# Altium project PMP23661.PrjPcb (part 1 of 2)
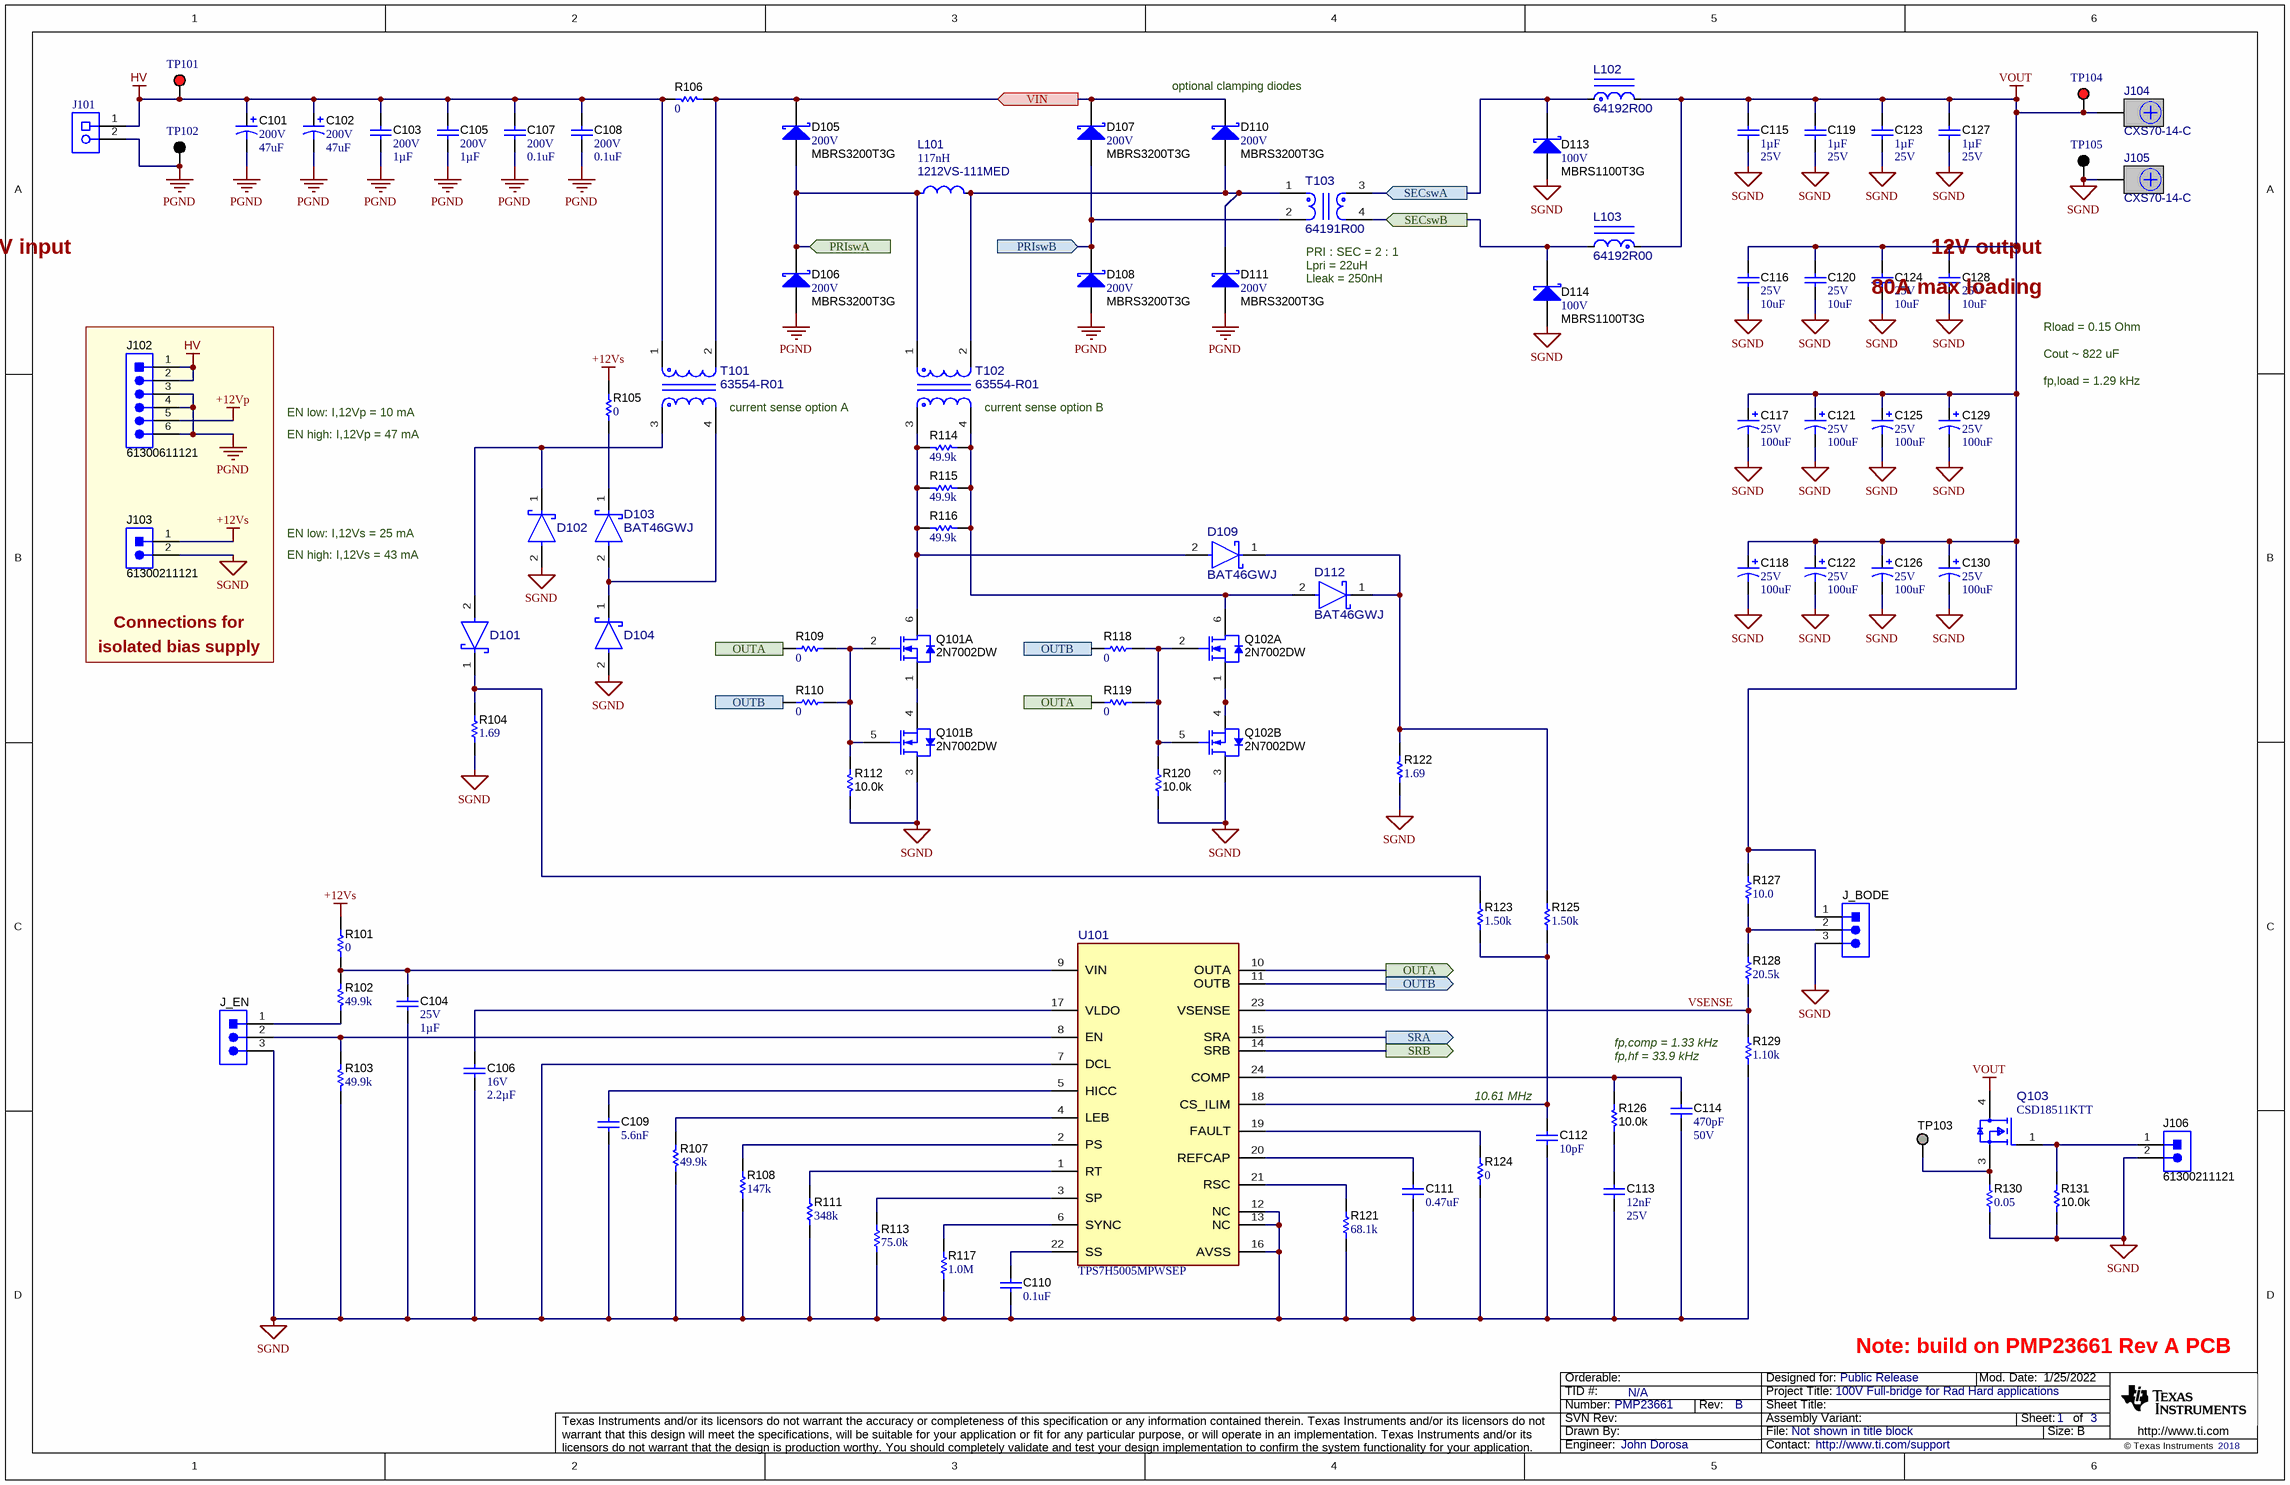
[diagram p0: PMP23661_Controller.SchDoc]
TID: N/A; TechSupport: http://www.ti.com/support; SCH_Rev: B; PRJ_Title: 100V Full-bridge for Rad Hard applications; PRJ_Number: PMP23661; PRJ_Engineer: John Dorosa; PRJ_Customer: Public Release; PCB_Rev: A; PCB_Layout: John Dorosa; CopyrightYear: 2018
3 sheets, 236 parts. Net scope: flat (ports and power ports of the same name join across sheets).
Board file: PMP23661.PcbDoc
Sheets:
  PMP23661_Controller.SchDoc
  PMP23661_Primary Drivers.SchDoc
  PMP23661_Secondary Drivers.SchDoc

## Sheet PMP23661_Controller.SchDoc
size 431 x 279 mm; Date: Not shown in title block; ApprovedBy: Not shown in title block; CheckedBy: Not shown in title block; Author: Not shown in title block; CompanyName: Not shown in title block; Engineer: Not shown in title block; Organization: Not shown in title block; Address1: Not shown in title block; Address2: Not shown in title block; Address3: Not shown in title block; Address4: Not shown in title block; DocumentNumber: 1; Revision: Use project parameter SCH_Rev; SheetNumber: 1; SheetTotal: 3; PageSetup: Record=PageOptions¦CenterHorizontal=True¦CenterVertical=True¦PrintScale=1.00¦XCorrection=1.00¦YCorrection=1.00¦PrintKind=0¦BorderSize=5000000¦LeftOffset=0¦BottomOffset=0¦Orientation=2¦PaperLength=1000¦PaperWidth=1000¦Scale=100¦PaperSource=15¦PrintQuality=600¦MediaType=1¦DitherType=10¦PaperKind=Letter¦PrintScaleMode=1

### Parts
C101  VDC_V: 200V  ValueDisplayed: 47uF  [EB_K16]  (hidden comment: EEV-EB2D470SM)
C102  VDC_V: 200V  ValueDisplayed: 47uF  [EB_K16]  (hidden comment: EEV-EB2D470SM)
C103  VDC_V: 200V  ValueDisplayed: 1µF  [1812_280]  (hidden comment: 18122C105KAT2A)
C104  VDC_V: 25V  Cap_F: 1µF  [0603_HV]  (hidden comment: GRM188R71E105KA12D)
C105  VDC_V: 200V  ValueDisplayed: 1µF  [1812_280]  (hidden comment: 18122C105KAT2A)
C106  VDC_V: 16V  Cap_F: 2.2µF  [0603_HV]  (hidden comment: GRM188Z71C225KE43)
C107  VDC_V: 200V  ValueDisplayed: 0.1uF  [1206_180]  (hidden comment: GRM31CR72D104KW03L)
C108  VDC_V: 200V  ValueDisplayed: 0.1uF  [1206_180]  (hidden comment: GRM31CR72D104KW03L)
C109  Cap_F: 5.6nF  [0603_HV]  (hidden comment: GRM188R71E562KA01D)
C110  value 0.1uF  [0603_HV]  (hidden comment: GCM188R71E104KA57D)
C111  value 0.47uF  [0603_HV]  (hidden comment: GCM188R71C474KA55D)
C112  ValueDisplayed: 10pF  [0603_HV]  (hidden comment: GCM1885C2A100JA16D)
C113  Cap_F: 12nF  VDC_V: 25V  [0603_HV]  (hidden comment: GRM188R71E123KA01D)
C114  Cap_F: 470pF  VDC_V: 50V  [0603_HV]  (hidden comment: GRM188R71H471KA01D)
C115  Cap_F: 1µF  VDC_V: 25V  [0805_HV]  (hidden comment: C0805C105K3RACTU)
C116  VDC_V: 25V  ValueDisplayed: 10uF  [1210_280]  (hidden comment: C1210C106K3RACTU)
C117  VDC_V: 25V  ValueDisplayed: 100uF  [7360-38]  (hidden comment: T495E107K025ATE100)
C118  VDC_V: 25V  ValueDisplayed: 100uF  [7360-38]  (hidden comment: T495E107K025ATE100)
C119  Cap_F: 1µF  VDC_V: 25V  [0805_HV]  (hidden comment: C0805C105K3RACTU)
C120  VDC_V: 25V  ValueDisplayed: 10uF  [1210_280]  (hidden comment: C1210C106K3RACTU)
C121  VDC_V: 25V  ValueDisplayed: 100uF  [7360-38]  (hidden comment: T495E107K025ATE100)
C122  VDC_V: 25V  ValueDisplayed: 100uF  [7360-38]  (hidden comment: T495E107K025ATE100)
C123  Cap_F: 1µF  VDC_V: 25V  [0805_HV]  (hidden comment: C0805C105K3RACTU)
C124  VDC_V: 25V  ValueDisplayed: 10uF  [1210_280]  (hidden comment: C1210C106K3RACTU)
C125  VDC_V: 25V  ValueDisplayed: 100uF  [7360-38]  (hidden comment: T495E107K025ATE100)
C126  VDC_V: 25V  ValueDisplayed: 100uF  [7360-38]  (hidden comment: T495E107K025ATE100)
C127  Cap_F: 1µF  VDC_V: 25V  [0805_HV]  (hidden comment: C0805C105K3RACTU)
C128  VDC_V: 25V  ValueDisplayed: 10uF  [1210_280]  (hidden comment: C1210C106K3RACTU)
C129  VDC_V: 25V  ValueDisplayed: 100uF  [7360-38]  (hidden comment: T495E107K025ATE100)
C130  VDC_V: 25V  ValueDisplayed: 100uF  [7360-38]  (hidden comment: T495E107K025ATE100)
D101  BAT46GWJ  [FP-BAT46GWJ_SOD-123-MFG]  (value not drawn)
D102  BAT46GWJ  [FP-BAT46GWJ_SOD-123-MFG]  (value not drawn)
D103  BAT46GWJ  [FP-BAT46GWJ_SOD-123-MFG]
D104  BAT46GWJ  [FP-BAT46GWJ_SOD-123-MFG]  (value not drawn)
D105  MBRS3200T3G  value 200V  [SMB]
D106  MBRS3200T3G  value 200V  [SMB]
D107  MBRS3200T3G  value 200V  [SMB]
D108  MBRS3200T3G  value 200V  [SMB]
D109  BAT46GWJ  [FP-BAT46GWJ_SOD-123-MFG]
D110  MBRS3200T3G  value 200V  [SMB]
D111  MBRS3200T3G  value 200V  [SMB]
D112  BAT46GWJ  [FP-BAT46GWJ_SOD-123-MFG]
D113  MBRS1100T3G  value 100V  [SMB]
D114  MBRS1100T3G  value 100V  [SMB]
J101  ED120/2DS  [On-Shore_ED120_2DS]  (value not drawn)
J102  61300611121  [WURTH_61300611121]
J103  61300211121  [WURTH_61300211121]
J104  CXS70-14-C  [Panduit_CXS70-14-C]
J105  CXS70-14-C  [Panduit_CXS70-14-C]
J106  61300211121  [WURTH_61300211121]
J_BODE  61300311121  [WURTH_61300311121]  (value not drawn)
J_EN  61300311121  [WURTH_61300311121]  (value not drawn)
L101  1212VS-111MED  value 117nH  [FP-1212VS-111MED_SMT_IND_11MM5_12MM0-MFG]
L102  64192R00  [FP-64192R00_PTH_IND_48MM0_33MM0-MFG]
L103  64192R00  [FP-64192R00_PTH_IND_48MM0_33MM0-MFG]
Q101  2N7002DW  [SOT-363]  (parts A,B of 2)
Q102  2N7002DW  [SOT-363]  (parts A,B of 2)
Q103  CSD18511KTT  [KTT0002A-MFG]
R101  ValueDisplayed: 0  [0603_HV]  (hidden comment: CRCW06030000Z0EA)
R102  ValueDisplayed: 49.9k  [0603_HV]  (hidden comment: CRCW060349K9FKEA)
R103  ValueDisplayed: 49.9k  [0603_HV]  (hidden comment: CRCW060349K9FKEA)
R104  ValueDisplayed: 1.69  [1206]  (hidden comment: CRCW12061R69FKEA)
R105  ValueDisplayed: 0  [0603_HV]  (hidden comment: CRCW06030000Z0EA)
R106  ValueDisplayed: 0  [2512_WIDE_VISHAY]  (hidden comment: RCL12250000Z0EG)
R107  ValueDisplayed: 49.9k  [0603_HV]  (hidden comment: CRCW060349K9FKEA)
R108  ValueDisplayed: 147k  [0603_HV]  (hidden comment: CRCW0603147KFKEA)
R109  ValueDisplayed: 0  [0603_HV]  (hidden comment: CRCW06030000Z0EA)
R110  ValueDisplayed: 0  [0603_HV]  (hidden comment: CRCW06030000Z0EA)
R111  ValueDisplayed: 348k  [0603_HV]  (hidden comment: CRCW0603348KFKEA)
R112  ValueDisplayed: 10.0k  [0603_HV]  (hidden comment: CRCW060310K0FKEA)
R113  ValueDisplayed: 75.0k  [0603_HV]  (hidden comment: CRCW060375K0FKEA)
R114  ValueDisplayed: 49.9k  [0603_HV]  (hidden comment: CRCW060349K9FKEA)
R115  ValueDisplayed: 49.9k  [0603_HV]  (hidden comment: CRCW060349K9FKEA)
R116  ValueDisplayed: 49.9k  [0603_HV]  (hidden comment: CRCW060349K9FKEA)
R117  ValueDisplayed: 1.0M  [0603_HV]  (hidden comment: CRCW06031M00JNEA)
R118  ValueDisplayed: 0  [0603_HV]  (hidden comment: CRCW06030000Z0EA)
R119  ValueDisplayed: 0  [0603_HV]  (hidden comment: CRCW06030000Z0EA)
R120  ValueDisplayed: 10.0k  [0603_HV]  (hidden comment: CRCW060310K0FKEA)
R121  ValueDisplayed: 68.1k  [0603_HV]  (hidden comment: CRCW060368K1FKEA)
R122  ValueDisplayed: 1.69  [1206]  (hidden comment: CRCW12061R69FKEA)
R123  ValueDisplayed: 1.50k  [0603_HV]  (hidden comment: CRCW06031K50FKEA)
R124  ValueDisplayed: 0  [0603_HV]  (hidden comment: CRCW06030000Z0EA)
R125  ValueDisplayed: 1.50k  [0603_HV]  (hidden comment: CRCW06031K50FKEA)
R126  ValueDisplayed: 10.0k  [0603_HV]  (hidden comment: CRCW060310K0FKEA)
R127  ValueDisplayed: 10.0  [0603_HV]  (hidden comment: CRCW060310R0FKEA)
R128  ValueDisplayed: 20.5k  [0603_HV]  (hidden comment: CRCW060320K5FKEA)
R129  ValueDisplayed: 1.10k  [0603_HV]  (hidden comment: CRCW06031K10FKEA)
R130  ValueDisplayed: 0.05  [3518_WIDE]  (hidden comment: FCSL90R050FER)
R131  ValueDisplayed: 10.0k  [0603_HV]  (hidden comment: CRCW060310K0FKEA)
T101  63554-R01  [FP-63554-R01_SMT_XFRMR_24MM0_20MM0-MFG]
T102  63554-R01  [FP-63554-R01_SMT_XFRMR_24MM0_20MM0-MFG]
T103  64191R00  [FP-64191R00_PTH_XFRMR_55MM0_48MM0-MFG]
TP101  5010  [Keystone5010]  (value not drawn)
TP102  5011  [Keystone5011]  (value not drawn)
TP103  TP_SM_1MM  [TP_SM_1MM]  (value not drawn)  (no BOM)
TP104  5010  [Keystone5010]  (value not drawn)
TP105  5011  [Keystone5011]  (value not drawn)
U101  TPS7H5005MPWSEP  [PW0024A-MFG]

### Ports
OUTA (in), OUTA (out), OUTB (in), OUTB (out), PRIswA (in), PRIswB (in), SECswA (in), SECswB (in), SRA (out), SRB (out), VIN (in)

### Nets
+12Vp: J102.5
+12Vs: J103.1 R101.2 R105.1
HV: C101.1(+) C102.1(+) C103.1 C105.1 C107.1 C108.1 J101.1 J102.1 J102.2 R106.2 T101.1 TP101.1
PGND: C101.2(-) C102.2(-) C103.2 C105.2 C107.2 C108.2 D106.2(A) D108.2(A) D111.2(A) J101.2 J102.3 J102.4 J102.6 TP102.1
SGND: C104.2 C106.1 C109.1 C110.2 C111.1 C112.2 C113.2 C114.2 C115.2 C116.2 C117.2(-) C118.2(-) C119.2 C120.2 C121.2(-) C122.2(-) C123.2 C124.2 C125.2(-) C126.2(-) C127.2 C128.2 C129.2(-) C130.2(-) D102.2(ANODE) D104.2(ANODE) D113.2(A) D114.2(A) J103.2 J105.1 J106.2 J_BODE.3 J_EN.3 Q101.3(D) Q102.3(D) R103.2 R104.1 R107.2 R108.1 R111.1 R112.1 R113.1 R117.1 R120.1 R121.1 R122.1 R124.2 R129.1 R130.1 R131.1 TP105.1 U101.7(DCL) U101.12(NC) U101.13(NC) U101.16(AVSS)
VOUT: C115.1 C116.1 C117.1(+) C118.1(+) C119.1 C120.1 C121.1(+) C122.1(+) C123.1 C124.1 C125.1(+) C126.1(+) C127.1 C128.1 C129.1(+) C130.1(+) J104.1 J_BODE.1 L102.2 L103.1 Q103.4(Drain) R127.2 TP104.1
OUTA: R109.2 R119.2 U101.10(OUTA) ; port OUTA
OUTB: R110.2 R118.2 U101.11(OUTB) ; port OUTB
PRIswA: D105.2(A) D106.1(K) L101.1 T102.1 ; port PRIswA
PRIswB: D107.2(A) D108.1(K) T103.2 ; port PRIswB
SECswA: D113.1(K) L102.1 T103.3 ; port SECswA
SECswB: D114.1(K) L103.2 T103.4 ; port SECswB
SRA: U101.15(SRA) ; port SRA
SRB: U101.14(SRB) ; port SRB
VIN: D105.1(K) D107.1(K) D110.1(K) R106.1 T101.2 ; port VIN
VSENSE: R128.1 R129.2 U101.23(VSENSE)
NetC104_1: C104.1 R101.1 R102.1 U101.9(VIN)
NetC106_2: C106.2 U101.17(VLDO)
NetC109_2: C109.2 U101.5(HICC)
NetC110_1: C110.1 U101.22(SS)
NetC111_2: C111.2 U101.20(REFCAP)
NetC112_1: C112.1 R123.1 R125.1 U101.18(CS_ILIM)
NetC113_1: C113.1 R126.1
NetC114_1: C114.1 R126.2 U101.24(COMP)
NetD101_1: D101.1(CATHODE) R104.2 R123.2
NetD101_2: D101.2(ANODE) D102.1(CATHODE) T101.3
NetD103_1: D103.1(CATHODE) R105.2
NetD103_2: D103.2(ANODE) D104.1(CATHODE) T101.4
NetD109_1: D109.1(CATHODE) D112.1(CATHODE) R122.2 R125.2
NetD109_2: D109.2(ANODE) Q101.6(D) R114.1 R115.1 R116.1 T102.3
NetD110_2: D110.2(A) D111.1(K) L101.2 T102.2 T103.1
NetD112_2: D112.2(ANODE) Q102.6(D) R114.2 R115.2 R116.2 T102.4
NetJ106_1: J106.1 Q103.1(Gate) R131.2
NetJ_BODE_2: J_BODE.2 R127.1 R128.2
NetJ_EN_1: J_EN.1 R102.2
NetJ_EN_2: J_EN.2 R103.1 U101.8(EN)
NetQ101_1: Q101.1(S) Q101.4(S)
NetQ101_2: Q101.2(G) Q101.5(G) R109.1 R110.1 R112.2
NetQ102_1: Q102.1(S) Q102.4(S)
NetQ102_2: Q102.2(G) Q102.5(G) R118.1 R119.1 R120.2
NetQ103_3: Q103.3(Source) R130.2 TP103.1
NetR107_1: R107.1 U101.4(LEB)
NetR108_2: R108.2 U101.2(PS)
NetR111_2: R111.2 U101.1(RT)
NetR113_2: R113.2 U101.3(SP)
NetR117_2: R117.2 U101.6(SYNC)
NetR121_2: R121.2 U101.21(RSC)
NetR124_1: R124.1 U101.19(FAULT)

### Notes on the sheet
- (near D110) optional clamping diodes
- 70 - 110V input
- (near T103) PRI : SEC = 2 : 1
- (near T103) Lpri = 22uH
- Lleak = 250nH
- 12V output
- 80A max loading
- Rload = 0.15 Ohm
- Cout ~ 822 uF
- EN low: I,12Vp = 10 mA
- EN high: I,12Vp = 47 mA
- (near T101) current sense option A
- (near T102) current sense option B
- fp,load = 1.29 kHz
- EN low: I,12Vs = 25 mA
- EN high: I,12Vs = 43 mA
- Connections for
- isolated bias supply
- (near C112) 10.61 MHz
- fp,hf = 33.9 kHz
- (near R129) fp,comp = 1.33 kHz
- Note: build on PMP23661 Rev A PCB

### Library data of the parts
C101 C102 = CMP-0011430-2: CAP, AL, 47 uF, 200 V, +/- 20%, SMD; Manufacturer: Panasonic; TaMin_C: -25°C; Polarized: Y; SizeAreaWB_mm2: 483; Value1: Unknown; U/M: EA; Value: 47uF; TaMax_C: 105°C; SizeZ_mm: 16.5; SizeX_mm: 21; SizeY_mm: 19; Cap_Case: 18x16.5; SizeArea_mm2: 399; CompType: Capacitor; AEC Qualified: N; Cap_F: 47µF; IRMS_A: 600mA; AEC Category: Q200
C103 C105 = CMP-0081058-1: CAP, CERM, 1 µF, 200 V,+/- 10%, X7R, 1812; Manufacturer: AVX; TaMin_C: -55°C; Polarized: N; SizeAreaWB_mm2: 23.1; U/M: EA; Value: 1uF; TaMax_C: 125°C; SizeZ_mm: 2.8; SizeX_mm: 4.5; SizeY_mm: 3.2; SizeArea_mm2: 14.4; AEC Category: Q200
C104 = CMP-0007405-5: CAP, CERM, 1 uF, 25 V, +/- 10%, X7R, 0603; Manufacturer: MuRata; Cap_Case: 0603; AEC Category: Q200; Value: 1uF; SizeX_mm: 1.6; U/M: EA; Value1: Unknown; SizeAreaWB_mm2: 4.68; SizeY_mm: 0.8; TaMin_C: -55°C; SizeZ_mm: 1; Polarized: N; MFG_Status: TI_Obsolete; TaMax_C: 125°C; SizeArea_mm2: 1.28
C106 = CMP-0007499-4: CAP, CERM, 2.2 uF, 16 V, +/- 10%, X7R, 0603; Manufacturer: MuRata; TaMin_C: -55°C; Polarized: N; SizeAreaWB_mm2: 4.68; Value1: Unknown; U/M: EA; Value: 2.2uF; TaMax_C: 125°C; SizeZ_mm: 1; SizeX_mm: 1.6; SizeY_mm: 0.8; Cap_Case: 0603; SizeArea_mm2: 1.28; AEC Category: Q200
C107 C108 = CMP-0008972-2: CAP, CERM, 0.1 uF, 200 V, +/- 10%, X7R, 1206; Manufacturer: MuRata; TaMin_C: -55°C; Polarized: N; SizeAreaWB_mm2: 10.92; Value1: Unknown; U/M: EA; Value: 0.1uF; TaMax_C: 125°C; SizeZ_mm: 1.8; SizeX_mm: 3.2; SizeY_mm: 1.6; Cap_Case: 3.2x16x16mm; SizeArea_mm2: 5.12; Cap_F: 100nF; AEC Category: Q200
C109 = CMP-0007425-5: CAP, CERM, 5600 pF, 25 V, +/- 10%, X7R, 0603; Manufacturer: MuRata; ValueDisplayed: 5600pF; SizeArea_mm2: 1.28; SizeZ_mm: 1; Value2: 25V; MFG_Status: TI_Obsolete; SizeX_mm: 1.6; Value1: Unknown; AEC Category: Q200; Value: 5600pF; SizeAreaWB_mm2: 4.68; Polarized: N; Cap_Case: 0603; U/M: EA; TaMin_C: -55°C; TaMax_C: 125°C; SizeY_mm: 0.8
C110 = CMP-0084679-1: CAP, CERM, 0.1 µF, 25 V,+/- 10%, X7R, AEC-Q200 Grade 1, 0603; Manufacturer: MuRata; VDC_V: 25V; TaMin_C: -55°C; SizeY_mm: 0.8; Polarized: N; SizeArea_mm2: 1.28; Cap_Case: 0603; SizeZ_mm: 1; SizeX_mm: 1.6; AEC Qualified: Y; AEC Category: Q200; ValueDisplayed: 0.1µF; TaMax_C: 125°C; U/M: EA; SizeAreaWB_mm2: 4.68; Cap_F: 100nF
C111 = CMP-0007138-4: CAP, CERM, 0.47 uF, 16 V, +/- 10%, X7R, AEC-Q200 Grade 1, 0603; Manufacturer: MuRata; TaMin_C: -55°C; Polarized: N; SizeAreaWB_mm2: 4.68; Value1: Unknown; U/M: EA; TaMax_C: 125°C; SizeZ_mm: 1; SizeX_mm: 1.6; SizeY_mm: 0.8; Cap_Case: 0603; Value2: 16V; SizeArea_mm2: 1.28; AEC Qualified: Y; Cap_F: 470nF; AEC Category: Q200
C112 = CMP-0084283-1: CAP, CERM, 10 pF, 100 V,+/- 5%, C0G/NP0, AEC-Q200 Grade 1, 0603; Manufacturer: MuRata; TaMax_C: 125°C; Cap_Case: 0603; Value2: 100V; SizeX_mm: 1.6; SizeY_mm: 0.8; SizeArea_mm2: 1.28; Polarized: N; AEC Category: Q200; SizeAreaWB_mm2: 4.68; AEC Qualified: Y; SizeZ_mm: 1; Value: 10pF; U/M: EA; TaMin_C: -55°C
C113 = CMP-0007407-5: CAP, CERM, 0.012 uF, 25 V, +/- 10%, X7R, 0603; Manufacturer: MuRata; SizeZ_mm: 1; SizeX_mm: 1.6; Polarized: N; SizeY_mm: 0.8; AEC Category: Q200; MFG_Status: TI_Obsolete; SizeAreaWB_mm2: 4.68; Cap_Case: 0603; SizeArea_mm2: 1.28; TaMax_C: 125°C; Value1: Unknown; U/M: EA; TaMin_C: -55°C
C114 = CMP-0007455-4: CAP, CERM, 470 pF, 50 V, +/- 10%, X7R, 0603; Manufacturer: MuRata; TaMin_C: -55°C; Polarized: N; SizeAreaWB_mm2: 4.68; Value1: Unknown; U/M: EA; Value: 470pF; TaMax_C: 125°C; SizeZ_mm: 1; SizeX_mm: 1.6; SizeY_mm: 0.8; Cap_Case: 0603; SizeArea_mm2: 1.28; AEC Category: Q200
C115 C119 C123 C127 = CMP-0007728-2: CAP, CERM, 1 uF, 25 V, +/- 10%, X7R, 0805; Manufacturer: Kemet; TaMin_C: -55°C; Polarized: N; SizeAreaWB_mm2: 6.75; Value1: Unknown; U/M: EA; Value: 1uF; TaMax_C: 125°C; SizeZ_mm: 1.45; SizeX_mm: 2; SizeY_mm: 1.25; Cap_Case: 0805; SizeArea_mm2: 2.5; AEC Category: Q200
C116 C120 C124 C128 = CMP-0009078-1: CAP, CERM, 10 uF, 25 V, +/- 10%, X7R, 1210; Manufacturer: Kemet; TaMin_C: -55°C; Polarized: N; SizeAreaWB_mm2: 14.7; Value1: Unknown; U/M: EA; Value: 10uF; TaMax_C: 125°C; SizeZ_mm: 2.8; SizeX_mm: 3.2; SizeY_mm: 2.5; Cap_Case: 1210; SizeArea_mm2: 8; Cap_F: 10µF; AEC Category: Q200
C117 C118 C121 C122 C125 C126 C129 C130 = CMP-0012025-2: CAP, TA, 100 uF, 25 V, +/- 10%, 0.1 ohm, SMD; Manufacturer: Kemet; TaMin_C: -55°C; ESR_ohm: 0.1; Polarized: Y; SizeAreaWB_mm2: 74.4; Value1: 0.1 ohm; U/M: EA; Value: 100uF; TaMax_C: 125°C; SizeZ_mm: 3.8; SizeX_mm: 7.3; SizeY_mm: 6; Cap_Case: E; SizeArea_mm2: 43.8; CompType: Capacitor; AEC Qualified: N; Cap_F: 100µF; IRMS_A: 1.273A; AEC Category: Q200
D101-D104 D109 D112 = CMP-0090343-1: Diode Schottky 100V 250mA (DC) Surface Mount SOD-123; Manufacturer: Nexperia; SizeZ_mm: 1.3mm; Peak Reverse Current: 2uA; TaMin_C: -55°C; Cap_F: 39pF; TJmax_C: 150°C; AEC Grade: Grade 0; Max Surge Forward Current: 2.5A; Standoff Height: 0mm; TaMax_C: +150°C; AEC Qualified: Yes
D105-D108 D110 D111 = CMP-0028599-2: Diode, Schottky, 200 V, 3 A, SMB; Manufacturer: ON Semiconductor; Io_A: 3A; SizeY_mm: 3.81; RJC_CperW: 62; SizeX_mm: 5.6; TJmax_C: 175°C; Vf_V: 840mV; SizeZ_mm: 2.6; Green_REACh: Incomplete; Green_Lifecycle: Not Set; AEC Category: Q101; SizeAreaWB_mm2: 44.156; Value2: 0.84V; SizeArea_mm2: 21.336
D113 D114 = CMP-0028521-2: Diode, Schottky, 100 V, 1 A, SMB; Manufacturer: ON Semiconductor; TJmax_C: 150°C; SizeY_mm: 3.81; RJC_CperW: 22; Value1: 1A; SizeAreaWB_mm2: 44.156; Green_Lifecycle: Active; SizeArea_mm2: 21.336; Vf_V: 750mV; SizeZ_mm: 2.6; SizeX_mm: 5.6; Green_REACh: Passed; Value2: 0.75V; AEC Category: Q101
J101 = CMP-0074910-1: Terminal Block, 5.08 mm, 2x1, Brass, TH; Manufacturer: On-Shore Technology; Cert_VDE: Y; CNHeader: False; Current_A: 15A; Green_Lifecycle: Not Set; Shrouded: N; Gender: Female; Green_REACh: Incomplete; Voltage_V: 300V; Row_Count: 1; Pitch_mm: 5.08; CT: True
J102 = CMP-0054801-2: Header, 2.54 mm, 6x1, Gold, TH; Manufacturer: Wurth Elektronik; Cert_UL: Y; Gender: Male; Row_Count: 1; Shrouded: N; Pitch_mm: 2.54
J103 J106 = CMP-0054794-2: Header, 2.54 mm, 2x1, Gold, TH; Manufacturer: Wurth Elektronik; Shrouded: N; Gender: Male; Green_REACh: Passed; Pitch_mm: 2.54; Green_Lifecycle: Active; Row_Count: 1; Cert_UL: Y
J104 J105 = CMP-0075010-2: Terminal 70A Lug; Manufacturer: Panduit; CompType: Screw Terminal; CT: False; Green_Lifecycle: Not Set; Green_REACh: Incomplete
J_BODE J_EN = CMP-0054796-4: Header, 2.54 mm, 3x1, Gold, TH; Manufacturer: Wurth Elektronik; Green_REACh: Passed; CT: FALSE; CNHeader: TRUE; Green_Lifecycle: Active
L101 = CMP-0125020-1: Air Core Inductor, High Current, 117 nH, 44 A, 1212VS Series, ± 20%, 0.00143 ohm, 399 MHz; Manufacturer: Coilcraft; AEC Qualified: No; DCR_ohm: 1.43m; Irms: 44A; SizeZ_mm: 11.3mm; Q Factor: 165; Self Resonant Frequency: 399MHz; TaMax_C: +125°C; TaMin_C: -40°C; Test Frequency: 1MHz
L102 L103 = CMP-0127672-1: 2uH & 48.7Ap INDUCTOR; Manufacturer: Payton Planar; Ind_H: 2µH; Irms: 48.7A; SizeZ_mm: 13mm
Q101 Q102 = CMP-0000770-1: MOSFET, 2-CH, N-CH, 60 V, 0.115 A, SOT-363; Alternate Manufacturer: None; Manufacturer: Fairchild Semiconductor; SizeZ_mm: 1.1; ChType: N; VdsMax_V: 60V; SizeX_mm: 2.2; Vgs_V: 20V; Value: 60V; SizeArea_mm2: 4.84; AEC Category: Q101; IdsMax_A: 115mA; SizeAreaWB_mm2: 10.24; U/M: EA
Q103 = CMP-0097579-1: MOSFET N-Channel 40 V 194A (Ta) 188W (Ta) Surface Mount DDPAK/TO-263-3; Manufacturer: Texas Instruments; Turn On Delay Time: 8ns; TJmax_C: +175°C; SizeZ_mm: 4.95mm; Standoff Height: 0mm; Reverse Recovery Charge: 62nC; Transconductance: 249S; IdsMax_A: 110A; Number Of N Channels: 1; AEC Qualified: No; Max Forward Diode Voltage: 1V; Rdson45_ohm: 2.1mΩ; VdsMax_V: 40V; QgTyp_nC: 64nC @ 10V; Input Capacitace At Vds: 4570pF @ 20V; Vgs_V: 20V; Turn Off Delay Time: 17ns; Threshold Vgs Min: 1.5V; Pulse Drain Current: 400A; Reverse Recovery Time: 31ns; Threshold Vgs Max: 2.4V; ChMode: False; Rthja Max: 62°C/W; Typ Forward Diode Voltage: 0.9V
R101 R105 R109 R110 R118 R119 R124 = CMP-0025697-4: RES, 0, 5%, 0.1 W, AEC-Q200 Grade 0, 0603; Manufacturer: Vishay-Dale; Power_W: 100mW; TempCo: 200 ppm/C; Value_Code: 0000; Value: 0; EIA_Code: E24; SizeX_mm: 1.6; SizeY_mm: 0.8; SizeZ_mm: 1; Value2: 0.1W; SizeArea_mm2: 1.28; AEC Qualified: Y; VDC_V: 75V; AEC Category: Q200
R102 R103 R107 R114-R116 = CMP-0022447-4: RES, 49.9 k, 1%, 0.1 W, AEC-Q200 Grade 0, 0603; Manufacturer: Vishay-Dale; Power_W: 100mW; TempCo: 100 ppm/C; Value_Code: 49k9; Value: 49.9k; EIA_Code: E96; SizeX_mm: 1.6; SizeY_mm: 0.8; SizeZ_mm: 1; Value2: 0.1W; SizeArea_mm2: 1.28; AEC Qualified: Y; VDC_V: 75V; AEC Category: Q200; AEC Grade: 0
R104 R122 = CMP-0016768-3: RES, 1.69, 1%, 0.25 W, AEC-Q200 Grade 0, 1206; Manufacturer: Vishay-Dale; Power_W: 250mW; TempCo: 100 ppm/C; Value_Code: 1R69; Value: 1.69; EIA_Code: E96; SizeX_mm: 3.2; SizeY_mm: 1.6; SizeZ_mm: 1.35; Value2: 0.25W; SizeArea_mm2: 5.12; AEC Qualified: Y; VDC_V: 200V; AEC Category: Q200; AEC Grade: 0
R106 = CMP-0015368-2: RES, 0, 5%, 2 W, 2512 WIDE; Manufacturer: Vishay Draloric; Power_W: 2W; TempCo: ppm/C; Value_Code: 0000; U/M: EA; Value: 0; EIA_Code: E24; AEC Category: Q200
R108 = CMP-0022052-4: RES, 147 k, 1%, 0.1 W, AEC-Q200 Grade 0, 0603; Manufacturer: Vishay-Dale; Power_W: 100mW; TempCo: 100 ppm/C; Value: 147k; EIA_Code: E96; SizeX_mm: 1.6; SizeY_mm: 0.8; SizeZ_mm: 1; Value2: 0.1W; SizeArea_mm2: 1.28; AEC Qualified: Y; VDC_V: 75V; AEC Category: Q200; AEC Grade: 0
R111 = CMP-0022344-4: RES, 348 k, 1%, 0.1 W, AEC-Q200 Grade 0, 0603; Manufacturer: Vishay-Dale; Power_W: 100mW; TempCo: 100 ppm/C; Value: 348k; EIA_Code: E96; SizeX_mm: 1.6; SizeY_mm: 0.8; SizeZ_mm: 1; Value2: 0.1W; SizeArea_mm2: 1.28; AEC Qualified: Y; VDC_V: 75V; AEC Category: Q200; AEC Grade: 0
R112 R120 R126 R131 = CMP-0021998-4: RES, 10.0 k, 1%, 0.1 W, AEC-Q200 Grade 0, 0603; Manufacturer: Vishay-Dale; Power_W: 100mW; TempCo: 100 ppm/C; Value_Code: 10k0; Value: 10.0k; EIA_Code: E96; Res_ohm: 10k; SizeX_mm: 1.6; SizeY_mm: 0.8; SizeZ_mm: 1; Value2: 0.1W; SizeArea_mm2: 1.28; AEC Qualified: Y; VDC_V: 75V; AEC Category: Q200; AEC Grade: 0
R113 = CMP-0022589-4: RES, 75.0 k, 1%, 0.1 W, AEC-Q200 Grade 0, 0603; Manufacturer: Vishay-Dale; Power_W: 100mW; TempCo: 100 ppm/C; Value_Code: 75k0; Value: 75.0k; EIA_Code: E96; Res_ohm: 75k; SizeX_mm: 1.6; SizeY_mm: 0.8; SizeZ_mm: 1; Value2: 0.1W; SizeArea_mm2: 1.28; AEC Qualified: Y; VDC_V: 75V; AEC Category: Q200; AEC Grade: 0
R117 = CMP-0025736-4: RES, 1.0 M, 5%, 0.1 W, AEC-Q200 Grade 0, 0603; Manufacturer: Vishay-Dale; Power_W: 100mW; TempCo: 200 ppm/C; Value_Code: 1M00; Value: 1.0Meg; EIA_Code: E24; Res_ohm: 1M; SizeX_mm: 1.6; SizeY_mm: 0.8; SizeZ_mm: 1; Value2: 0.1W; SizeArea_mm2: 1.28; AEC Qualified: Y; VDC_V: 75V; AEC Category: Q200; AEC Grade: 0
R121 = CMP-0022552-4: RES, 68.1 k, 1%, 0.1 W, AEC-Q200 Grade 0, 0603; Manufacturer: Vishay-Dale; Power_W: 100mW; TempCo: 100 ppm/C; Value_Code: 68k1; Value: 68.1k; EIA_Code: E96; SizeX_mm: 1.6; SizeY_mm: 0.8; SizeZ_mm: 1; Value2: 0.1W; SizeArea_mm2: 1.28; AEC Qualified: Y; VDC_V: 75V; AEC Category: Q200; AEC Grade: 0
R123 R125 = CMP-0022126-4: RES, 1.50 k, 1%, 0.1 W, AEC-Q200 Grade 0, 0603; Manufacturer: Vishay-Dale; Power_W: 100mW; TempCo: 100 ppm/C; Value_Code: 1k50; Value: 1.50k; EIA_Code: E96; Res_ohm: 1.5k; SizeX_mm: 1.6; SizeY_mm: 0.8; SizeZ_mm: 1; Value2: 0.1W; SizeArea_mm2: 1.28; AEC Qualified: Y; VDC_V: 75V; AEC Category: Q200; AEC Grade: 0
R127 = CMP-0022003-4: RES, 10.0, 1%, 0.1 W, AEC-Q200 Grade 0, 0603; Manufacturer: Vishay-Dale; Power_W: 100mW; TempCo: 100 ppm/C; Value_Code: 10R0; Value: 10.0; EIA_Code: E96; Res_ohm: 10; SizeX_mm: 1.6; SizeY_mm: 0.8; SizeZ_mm: 1; Value2: 0.1W; SizeArea_mm2: 1.28; AEC Qualified: Y; VDC_V: 75V; AEC Category: Q200; AEC Grade: 0
R128 = CMP-0022205-4: RES, 20.5 k, 1%, 0.1 W, AEC-Q200 Grade 0, 0603; Manufacturer: Vishay-Dale; Power_W: 100mW; TempCo: 100 ppm/C; Value_Code: 20k5; Value: 20.5k; EIA_Code: E96; SizeX_mm: 1.6; SizeY_mm: 0.8; SizeZ_mm: 1; Value2: 0.1W; SizeArea_mm2: 1.28; AEC Qualified: Y; VDC_V: 75V; AEC Category: Q200; AEC Grade: 0
R129 = CMP-0022113-4: RES, 1.10 k, 1%, 0.1 W, AEC-Q200 Grade 0, 0603; Manufacturer: Vishay-Dale; Power_W: 100mW; TempCo: 100 ppm/C; Value_Code: 1k10; Value: 1.10k; EIA_Code: E96; Res_ohm: 1.1k; SizeX_mm: 1.6; SizeY_mm: 0.8; SizeZ_mm: 1; Value2: 0.1W; SizeArea_mm2: 1.28; AEC Qualified: Y; VDC_V: 75V; AEC Category: Q200; AEC Grade: 0
R130 = CMP-0015082-2: RES, 0.05, 1%, 4 W, 3518 WIDE; Manufacturer: Ohmite; Power_W: 4W; TempCo: 50 ppm/C; SizeAreaWB_mm2: 79.52; Value_Code: R050; U/M: EA; Value: 0.05; EIA_Code: E96; Res_ohm: 50m; SizeX_mm: 9.2; SizeY_mm: 5.1; SizeZ_mm: 0.7; SizeArea_mm2: 46.92; VDC_V: 0V; AEC Category: Q200
T101 T102 = CMP-0122471-1: Current Transformer 1:50; Manufacturer: Payton Planar; SizeZ_mm: 9mm; AEC Qualified: No
T103 = CMP-0127699-1: TITLE 1000W SMPS TRANSFORMER; Manufacturer: Payton Planar; SizeZ_mm: 15mm
TP101 TP104 = CMP-0055147-2: Test Point, Multipurpose, Red, TH; Manufacturer: Keystone Electronics; CT: TRUE; ContactFinish: Silver; Green_Lifecycle: Active; CNHeader: FALSE; Green_REACh: Passed
TP102 TP105 = CMP-0055148-2: Test Point, Multipurpose, Black, TH; Manufacturer: Keystone Electronics; CNHeader: FALSE; ContactFinish: Silver; Green_REACh: Passed; Green_Lifecycle: Active; CT: TRUE
TP103 = CMP-0003825-1: 1mm Test Point, SMT; Manufacturer: Any
U101 = CMP-0092938-1: Manufacturer: Texas Instruments; AEC Qualified: No; SizeZ_mm: 1.2mm; Standoff Height: 0.05mm

## Sheet PMP23661_Primary Drivers.SchDoc
size 431 x 279 mm; Date: Not shown in title block; ApprovedBy: Not shown in title block; CheckedBy: Not shown in title block; Author: Not shown in title block; CompanyName: Not shown in title block; Engineer: Not shown in title block; Organization: Not shown in title block; Address1: Not shown in title block; Address2: Not shown in title block; Address3: Not shown in title block; Address4: Not shown in title block; DocumentNumber: 2; Revision: Use project parameter SCH_Rev; SheetNumber: 2; SheetTotal: 3; PageSetup: Record=PageOptions¦CenterHorizontal=True¦CenterVertical=True¦PrintScale=1.00¦XCorrection=1.00¦YCorrection=1.00¦PrintKind=0¦BorderSize=5000000¦LeftOffset=0¦BottomOffset=0¦Orientation=2¦PaperLength=1000¦PaperWidth=1000¦Scale=100¦PaperSource=15¦PrintQuality=600¦MediaType=1¦DitherType=10¦PaperKind=Letter¦PrintScaleMode=1
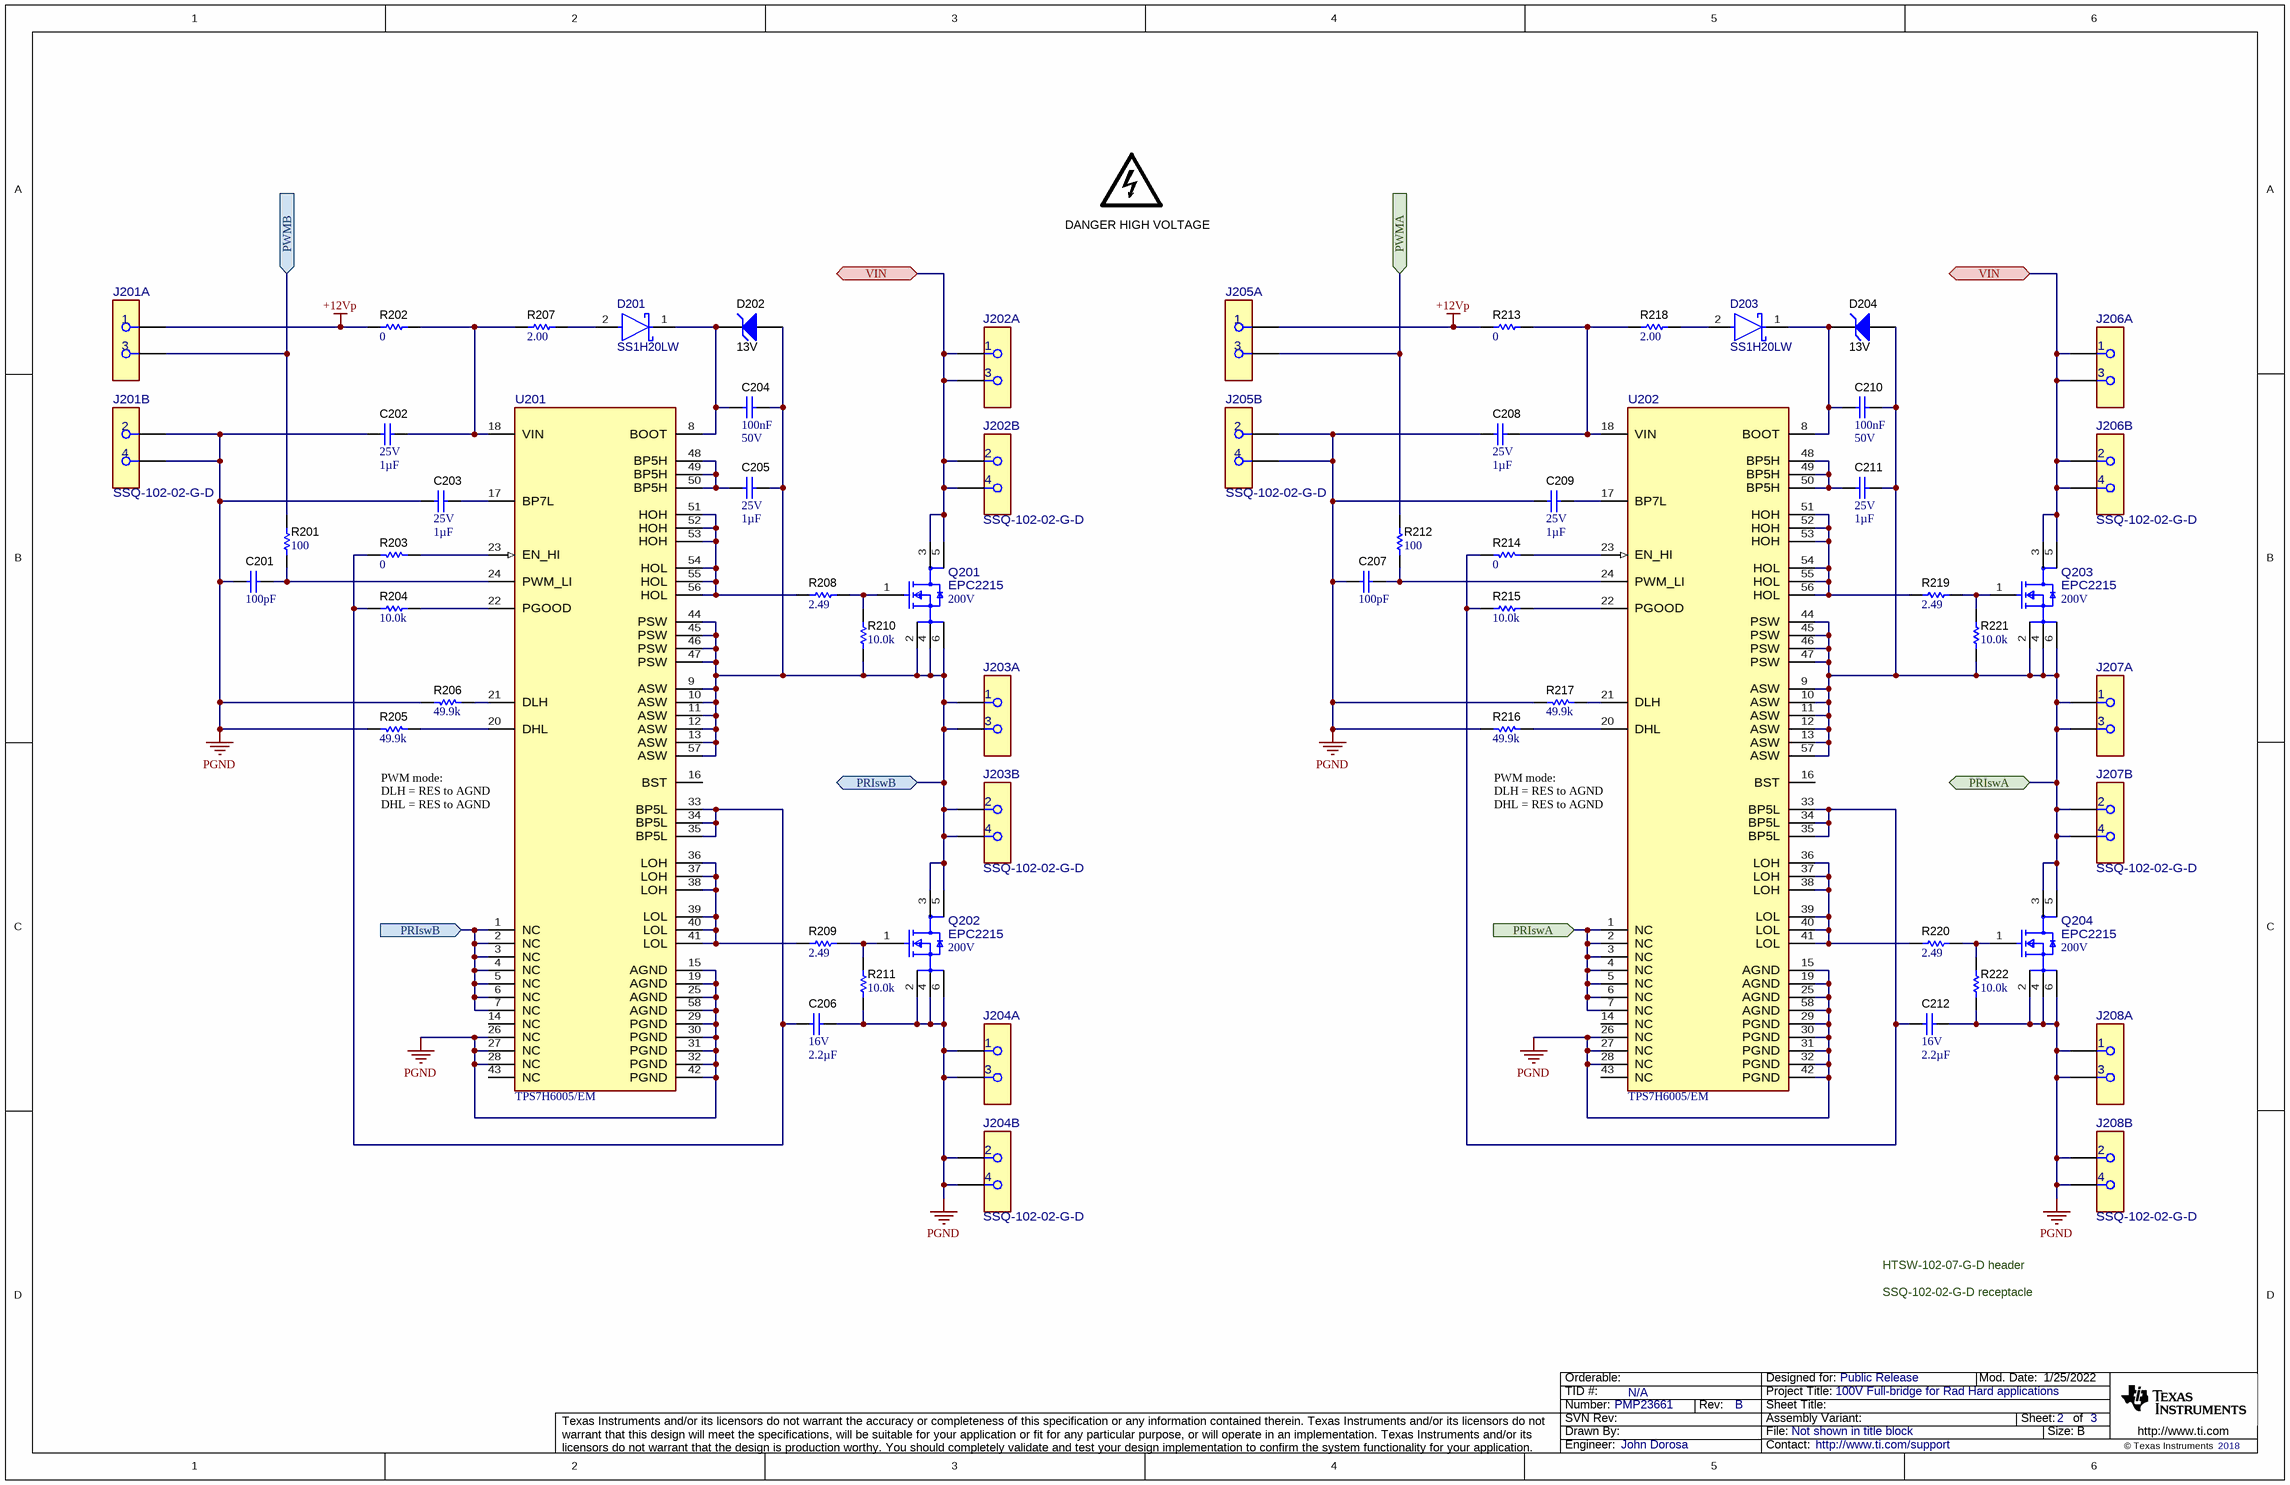
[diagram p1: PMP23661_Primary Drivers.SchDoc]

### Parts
C201  ValueDisplayed: 100pF  [0603_HV]  (hidden comment: GRM1885C1H101JA01D)
C202  VDC_V: 25V  Cap_F: 1µF  [0603_HV]  (hidden comment: GRM188R71E105KA12D)
C203  VDC_V: 25V  Cap_F: 1µF  [0603_HV]  (hidden comment: GRM188R71E105KA12D)
C204  Cap_F: 100nF  VDC_V: 50V  [0603_HV]  (hidden comment: C0603C104K5RACAUTO)
C205  VDC_V: 25V  Cap_F: 1µF  [0603_HV]  (hidden comment: GRM188R71E105KA12D)
C206  VDC_V: 16V  Cap_F: 2.2µF  [0603_HV]  (hidden comment: GRM188Z71C225KE43)
C207  ValueDisplayed: 100pF  [0603_HV]  (hidden comment: GRM1885C1H101JA01D)
C208  VDC_V: 25V  Cap_F: 1µF  [0603_HV]  (hidden comment: GRM188R71E105KA12D)
C209  VDC_V: 25V  Cap_F: 1µF  [0603_HV]  (hidden comment: GRM188R71E105KA12D)
C210  Cap_F: 100nF  VDC_V: 50V  [0603_HV]  (hidden comment: C0603C104K5RACAUTO)
C211  VDC_V: 25V  Cap_F: 1µF  [0603_HV]  (hidden comment: GRM188R71E105KA12D)
C212  VDC_V: 16V  Cap_F: 2.2µF  [0603_HV]  (hidden comment: GRM188Z71C225KE43)
D201  SS1H20LW  [FP-SS1H20LW_SOD-123W-MFG]
D202  value 13V  [SOD-123]  (hidden comment: MMSZ5243B-7-F)
D203  SS1H20LW  [FP-SS1H20LW_SOD-123W-MFG]
D204  value 13V  [SOD-123]  (hidden comment: MMSZ5243B-7-F)
J201  SSQ-102-02-G-D  [FP-SSQ-102-02-G-D_CONN_RCPT_4-MFG]  (value not drawn)  (parts A,B of 2)
J202  SSQ-102-02-G-D  [FP-SSQ-102-02-G-D_CONN_RCPT_4-MFG]  (value not drawn)  (parts A,B of 2)
J203  SSQ-102-02-G-D  [FP-SSQ-102-02-G-D_CONN_RCPT_4-MFG]  (value not drawn)  (parts A,B of 2)
J204  SSQ-102-02-G-D  [FP-SSQ-102-02-G-D_CONN_RCPT_4-MFG]  (value not drawn)  (parts A,B of 2)
J205  SSQ-102-02-G-D  [FP-SSQ-102-02-G-D_CONN_RCPT_4-MFG]  (value not drawn)  (parts A,B of 2)
J206  SSQ-102-02-G-D  [FP-SSQ-102-02-G-D_CONN_RCPT_4-MFG]  (value not drawn)  (parts A,B of 2)
J207  SSQ-102-02-G-D  [FP-SSQ-102-02-G-D_CONN_RCPT_4-MFG]  (value not drawn)  (parts A,B of 2)
J208  SSQ-102-02-G-D  [FP-SSQ-102-02-G-D_CONN_RCPT_4-MFG]  (value not drawn)  (parts A,B of 2)
LOGO201  DANGER HIGH VOLTAGE  [IEC_HighVoltage_Medium]  (no BOM)
Q201  EPC2215  VdsMax_V: 200V  [FP-EPC2215_LGA6-MFG]
Q202  EPC2215  VdsMax_V: 200V  [FP-EPC2215_LGA6-MFG]
Q203  EPC2215  VdsMax_V: 200V  [FP-EPC2215_LGA6-MFG]
Q204  EPC2215  VdsMax_V: 200V  [FP-EPC2215_LGA6-MFG]
R201  ValueDisplayed: 100  [0603_HV]  (hidden comment: CRCW0603100RJNEA)
R202  ValueDisplayed: 0  [0603_HV]  (hidden comment: CRCW06030000Z0EA)
R203  ValueDisplayed: 0  [0603_HV]  (hidden comment: CRCW06030000Z0EA)
R204  ValueDisplayed: 10.0k  [0603_HV]  (hidden comment: CRCW060310K0FKEA)
R205  ValueDisplayed: 49.9k  [0603_HV]  (hidden comment: CRCW060349K9FKEA)
R206  ValueDisplayed: 49.9k  [0603_HV]  (hidden comment: CRCW060349K9FKEA)
R207  ValueDisplayed: 2.00  [0603_HV]  (hidden comment: MCT06030C2008FP500)
R208  ValueDisplayed: 2.49  [0603_HV]  (hidden comment: CRCW06032R49FKEA)
R209  ValueDisplayed: 2.49  [0603_HV]  (hidden comment: CRCW06032R49FKEA)
R210  ValueDisplayed: 10.0k  [0603_HV]  (hidden comment: CRCW060310K0FKEA)
R211  ValueDisplayed: 10.0k  [0603_HV]  (hidden comment: CRCW060310K0FKEA)
R212  ValueDisplayed: 100  [0603_HV]  (hidden comment: CRCW0603100RJNEA)
R213  ValueDisplayed: 0  [0603_HV]  (hidden comment: CRCW06030000Z0EA)
R214  ValueDisplayed: 0  [0603_HV]  (hidden comment: CRCW06030000Z0EA)
R215  ValueDisplayed: 10.0k  [0603_HV]  (hidden comment: CRCW060310K0FKEA)
R216  ValueDisplayed: 49.9k  [0603_HV]  (hidden comment: CRCW060349K9FKEA)
R217  ValueDisplayed: 49.9k  [0603_HV]  (hidden comment: CRCW060349K9FKEA)
R218  ValueDisplayed: 2.00  [0603_HV]  (hidden comment: MCT06030C2008FP500)
R219  ValueDisplayed: 2.49  [0603_HV]  (hidden comment: CRCW06032R49FKEA)
R220  ValueDisplayed: 2.49  [0603_HV]  (hidden comment: CRCW06032R49FKEA)
R221  ValueDisplayed: 10.0k  [0603_HV]  (hidden comment: CRCW060310K0FKEA)
R222  ValueDisplayed: 10.0k  [0603_HV]  (hidden comment: CRCW060310K0FKEA)
U201  TPS7H6005/EM  [DCA0056M-MFG]
U202  TPS7H6005/EM  [DCA0056M-MFG]

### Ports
PRIswA (bidir), PRIswA (in), PRIswB (bidir), PRIswB (in), PWMA (in), PWMB (in), VIN (bidir)

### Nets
+12Vp: J201.1 J205.1 R202.1 R213.1
PGND: C201.2 C202.2 C203.1 C206.1 C207.1 C208.2 C209.1 C212.1 J201.2 J201.4 J204.1 J204.2 J204.3 J204.4 J205.2 J205.4 J208.1 J208.2 J208.3 J208.4 Q202.2(Source) Q202.4(Source) Q202.6(Source) Q204.2(Source) Q204.4(Source) Q204.6(Source) R205.2 R206.2 R211.2 R216.2 R217.2 R222.2 U201.15(AGND) U201.19(AGND) U201.25(AGND) U201.26(NC) U201.27(NC) U201.28(NC) U201.29(PGND) U201.30(PGND) U201.31(PGND) U201.32(PGND) U201.42(PGND) U201.58(AGND) U202.15(AGND) U202.19(AGND) U202.25(AGND) U202.26(NC) U202.27(NC) U202.28(NC) U202.29(PGND) U202.30(PGND) U202.31(PGND) U202.32(PGND) U202.42(PGND) U202.58(AGND)
PRIswA: C210.1 C211.1 D204.2(A) J207.1 J207.2 J207.3 J207.4 Q203.2(Source) Q203.4(Source) Q203.6(Source) Q204.3(Drain) Q204.5(Drain) R221.2 U202.1(NC) U202.2(NC) U202.3(NC) U202.4(NC) U202.5(NC) U202.6(NC) U202.7(NC) U202.9(ASW) U202.10(ASW) U202.11(ASW) U202.12(ASW) U202.13(ASW) U202.44(PSW) U202.45(PSW) U202.46(PSW) U202.47(PSW) U202.57(ASW) ; port PRIswA
PRIswB: C204.1 C205.1 D202.2(A) J203.1 J203.2 J203.3 J203.4 Q201.2(Source) Q201.4(Source) Q201.6(Source) Q202.3(Drain) Q202.5(Drain) R210.2 U201.1(NC) U201.2(NC) U201.3(NC) U201.4(NC) U201.5(NC) U201.6(NC) U201.7(NC) U201.9(ASW) U201.10(ASW) U201.11(ASW) U201.12(ASW) U201.13(ASW) U201.44(PSW) U201.45(PSW) U201.46(PSW) U201.47(PSW) U201.57(ASW) ; port PRIswB
PWMA: J205.3 R212.2 ; port PWMA
PWMB: J201.3 R201.2 ; port PWMB
VIN: J202.1 J202.2 J202.3 J202.4 J206.1 J206.2 J206.3 J206.4 Q201.3(Drain) Q201.5(Drain) Q203.3(Drain) Q203.5(Drain) ; port VIN
NetC201_1: C201.1 R201.1 U201.24(PWM_LI)
NetC202_1: C202.1 R202.2 R207.1 U201.18(VIN)
NetC203_2: C203.2 U201.17(BP7L)
NetC204_2: C204.2 D201.1(CATHODE) D202.1(K) U201.8(BOOT)
NetC205_2: C205.2 U201.48(BP5H) U201.49(BP5H) U201.50(BP5H)
NetC206_2: C206.2 R203.1 R204.2 U201.33(BP5L) U201.34(BP5L) U201.35(BP5L)
NetC207_2: C207.2 R212.1 U202.24(PWM_LI)
NetC208_1: C208.1 R213.2 R218.1 U202.18(VIN)
NetC209_2: C209.2 U202.17(BP7L)
NetC210_2: C210.2 D203.1(CATHODE) D204.1(K) U202.8(BOOT)
NetC211_2: C211.2 U202.48(BP5H) U202.49(BP5H) U202.50(BP5H)
NetC212_2: C212.2 R214.1 R215.2 U202.33(BP5L) U202.34(BP5L) U202.35(BP5L)
NetD201_2: D201.2(ANODE) R207.2
NetD203_2: D203.2(ANODE) R218.2
NetQ201_1: Q201.1(Gate) R208.1 R210.1
NetQ202_1: Q202.1(Gate) R209.1 R211.1
NetQ203_1: Q203.1(Gate) R219.1 R221.1
NetQ204_1: Q204.1(Gate) R220.1 R222.1
NetR203_2: R203.2 U201.23(EN_HI)
NetR204_1: R204.1 U201.22(PGOOD)
NetR205_1: R205.1 U201.20(DHL)
NetR206_1: R206.1 U201.21(DLH)
NetR208_2: R208.2 U201.51(HOH) U201.52(HOH) U201.53(HOH) U201.54(HOL) U201.55(HOL) U201.56(HOL)
NetR209_2: R209.2 U201.36(LOH) U201.37(LOH) U201.38(LOH) U201.39(LOL) U201.40(LOL) U201.41(LOL)
NetR214_2: R214.2 U202.23(EN_HI)
NetR215_1: R215.1 U202.22(PGOOD)
NetR216_1: R216.1 U202.20(DHL)
NetR217_1: R217.1 U202.21(DLH)
NetR219_2: R219.2 U202.51(HOH) U202.52(HOH) U202.53(HOH) U202.54(HOL) U202.55(HOL) U202.56(HOL)
NetR220_2: R220.2 U202.36(LOH) U202.37(LOH) U202.38(LOH) U202.39(LOL) U202.40(LOL) U202.41(LOL)

Not connected (* = marked no-connect by the designer): U201 14(NC) 16(BST) 43(NC); U202 14(NC) 16(BST) 43(NC)

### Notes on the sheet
- (near U201) PWM mode:
  DLH = RES to AGND
  DHL = RES to AGND
- (near U202) PWM mode:
  DLH = RES to AGND
  DHL = RES to AGND
- SSQ-102-02-G-D receptacle
- HTSW-102-07-G-D header

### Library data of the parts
C201 C207 = CMP-0007171-4: CAP, CERM, 100 pF, 50 V, +/- 5%, C0G/NP0, 0603; Manufacturer: MuRata; TaMin_C: -55°C; Polarized: N; SizeAreaWB_mm2: 4.68; Value1: Unknown; U/M: EA; Value: 100pF; TaMax_C: 125°C; SizeZ_mm: 1; SizeX_mm: 1.6; SizeY_mm: 0.8; Cap_Case: 0603; Value2: 50V; SizeArea_mm2: 1.28; AEC Category: Q200
C202 C203 C205 C208 C209 C211 = CMP-0007405-5: as C104 on sheet PMP23661_Controller
C204 C210 = CMP-0079602-1: CAP, CERM, 0.1 µF, 50 V,+/- 10%, X7R, AEC-Q200 Grade 1, 0603; Manufacturer: Kemet; TaMin_C: -55°C; Polarized: N; SizeAreaWB_mm2: 4.68; U/M: EA; Value: 0.1uF; TaMax_C: 125°C; SizeZ_mm: 1; SizeX_mm: 1.6; SizeY_mm: 0.8; Cap_Case: 0603; SizeArea_mm2: 1.28; AEC Qualified: Y; AEC Category: Q200; ValueDisplayed: 0.1µF
C206 C212 = CMP-0007499-4: as C106 on sheet PMP23661_Controller
D201 D203 = CMP-0095320-1: Diode Schottky 200 V 1A Surface Mount SOD-123W; Manufacturer: Taiwan Semiconductor; Max Surge Forward Current: 30A; SizeZ_mm: 1.02mm; AEC Qualified: No; Vf_V: 200V; TJmax_C: 175°C; Peak Reverse Current: 0.1mA; Standoff Height: 0mm
D202 D204 = CMP-0005752-4: Diode, Zener, 13 V, 500 mW, SOD-123; Manufacturer: Diodes Inc.; Value1: 0.5W; SizeAreaWB_mm2: 13.095; RJA_CperW: 350; AEC Category: Q101; SizeZ_mm: 1.35; SizeX_mm: 3.85; Power_W: 500mW; SizeArea_mm2: 6.545; SizeY_mm: 1.7
J201-J208 = CMP-0127928-1: Conn Socket Strip SKT 4 POS 2.54mm Solder ST Top Entry Thru-Hole Bulk; Manufacturer: Samtec; ContactFinish: Gold,Nickel; Current_A: 6.3A; Row_Count: 2; Voltage_V: 655V; AEC Qualified: No; Conn Gender: Female; Conn Orientation: Straight; Is Female: yes; SizeZ_mm: 8.64mm
LOGO201 = CMP-0074835-1: IEC 61010-1 High Voltage Warning; SymbolCreator: a0412235
Q201-Q204 = CMP-0033803-1: MOSFET N-Channel 200 V 32A (Ta) Surface Mount Die; Manufacturer: EPC; AEC Qualified: No; QgTyp_nC: 13.6nC @ 5V; Rdson45_ohm: 6m; SizeZ_mm: 0.675mm; Vgs_V: 6V; ChMode: False; Input Capacitace At Vds: 1356pF @ 100V; Number Of Channels: 1; Pulse Drain Current: 162A; Rthja Max: 52°C/W; Standoff Height: 0.108mm; Threshold Vgs Max: 2.5V; Threshold Vgs Min: 0.8V; TJmax_C: +150°C; Typ Forward Diode Voltage: 1.6V
R201 R212 = CMP-0025700-4: RES, 100, 5%, 0.1 W, AEC-Q200 Grade 0, 0603; Manufacturer: Vishay-Dale; Power_W: 100mW; TempCo: 200 ppm/C; Value_Code: 100R; Value: 100; EIA_Code: E24; SizeX_mm: 1.6; SizeY_mm: 0.8; SizeZ_mm: 1; Value2: 0.1W; SizeArea_mm2: 1.28; AEC Qualified: Y; VDC_V: 75V; AEC Category: Q200; AEC Grade: 0
R202 R203 R213 R214 = CMP-0025697-4: as R101 on sheet PMP23661_Controller
R204 R210 R211 R215 R221 R222 = CMP-0021998-4: as R112 on sheet PMP23661_Controller
R205 R206 R216 R217 = CMP-0022447-4: as R102 on sheet PMP23661_Controller
R207 R218 = CMP-0022732-2: RES, 2.00, 1%, 0.125 W, 0603; Manufacturer: Vishay/Beyschlag; Power_W: 125mW; TempCo: 50 ppm/C; Value_Code: 2R00; U/M: EA; Value: 2.00; EIA_Code: E96; Res_ohm: 2; SizeX_mm: 1.6; SizeY_mm: 0.8; Value2: 0.125W; SizeArea_mm2: 1.28; AEC Qualified: N; AEC Category: Q200; SizeZ_mm: 1
R208 R209 R219 R220 = CMP-0022311-4: RES, 2.49, 1%, 0.1 W, AEC-Q200 Grade 0, 0603; Manufacturer: Vishay-Dale; Power_W: 100mW; TempCo: 100 ppm/C; Value_Code: 2R49; Value: 2.49; EIA_Code: E96; SizeX_mm: 1.6; SizeY_mm: 0.8; SizeZ_mm: 1; Value2: 0.1W; SizeArea_mm2: 1.28; AEC Qualified: Y; VDC_V: 75V; AEC Category: Q200; AEC Grade: 0
U201 U202 = CMP-0120202-4: Manufacturer: Texas Instruments; SizeZ_mm: 1.2mm; Standoff Height: 0.05mm; AEC Category: Q200; CompType: IC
